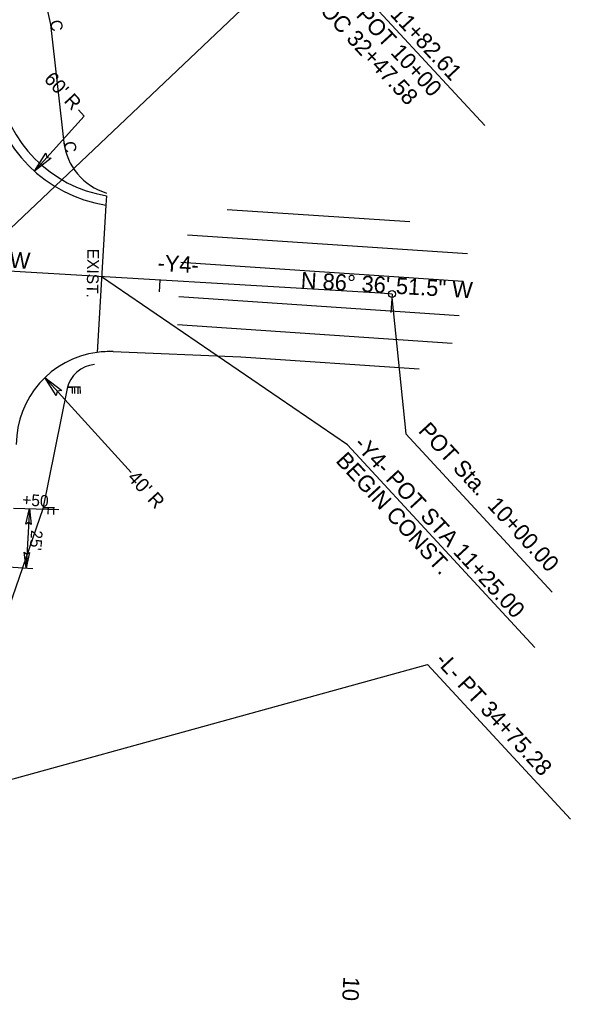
# Model space of a CAD drawing. Extents: x 1702862 to 1704514, y 793768 to 796215.
# Drawn here: x 1704008.6 to 1704245.2, y 793885.2 to 794306.9 of the extents above; entities that cross this region are included whole.
import ezdxf

# ---------------------------------------------------------------- set-up
doc = ezdxf.new("R2010")
doc.units = 0
for name, color, linetype in [('Exist Horizontal Alignment', 7, 'Continuous'), ('Prop Dimension', 7, 'Continuous'), ('Prop DSN Text', 7, 'Continuous'), ('Prop EOT', 7, 'Continuous'), ('Prop Horizontal Alignment', 7, 'Continuous'), ('Prop Horizontal Alignment Direction Label', 7, 'Continuous'), ('Prop Horizontal Alignment Station Label', 7, 'Continuous'), ('Prop Horizontal Alignment Tick Label', 7, 'Continuous'), ('Prop Horizontal Alignment Tick Large', 7, 'Continuous'), ('Prop Horizontal Alignment Tick Small', 7, 'Continuous'), ('Prop Lane Lines', 7, 'Continuous'), ('Prop Leader Line Medium', 7, 'Continuous'), ('Prop Paved Shoulder', 7, 'Continuous'), ('Prop SS Cut Line', 7, 'Continuous'), ('Prop SS Fill Line', 7, 'Continuous'), ('Prop SS Misc', 7, 'Continuous'), ('Prop SS Transition Line', 7, 'Continuous'), ('Prop Superelevation Label', 7, 'Continuous'), ('Prop Terminator CELL', 7, 'Continuous')]:
    doc.layers.add(name, color=color, linetype=linetype)

msp = doc.modelspace()

# ---------------------------------------------------------------- linework, layer by layer
at = {"layer": 'Exist Horizontal Alignment'}
msp.add_line((1704168.58, 794188.93), (1704163.59, 794189.23), dxfattribs=at)
at = {"layer": 'Prop Dimension'}
for points in [[(1704033.81, 794268.08), (1704036.35, 794265.34), (1704014.88, 794241.77)], [(1704056.52, 794112.19), (1704053.8, 794115.14), (1704019.4, 794153.02)]]:
    msp.add_lwpolyline(points, dxfattribs=at)
at = {"layer": 'Prop EOT'}
msp.add_line((1704045.63, 794227.2), (1704041.88, 794163.83), dxfattribs=at)
for centre, radius, start, end in [((1704054.89, 794286.48), 60, 188.634, 261.1171), ((1704047.11, 794124.17), 40, 97.5132, 179.9743)]:
    msp.add_arc(centre, radius, start, end, dxfattribs=at)
at = {"layer": 'Prop Horizontal Alignment'}
for p, q in [((1704163.59, 794189.23), (1703986.29, 794199.72)), ((1704168.58, 794188.93), (1704163.59, 794189.23))]:
    msp.add_line(p, q, dxfattribs=at)
at = {"layer": 'Prop Horizontal Alignment Station Label'}
for p, q in [((1703986.29, 794199.72), (1704135, 794340.88)), ((1704135, 794340.88), (1704208.42, 794261.33)), ((1704168.49, 794187.44), (1704174.54, 794128.85)), ((1704174.54, 794128.85), (1704237.37, 794060.78)), ((1703977.5, 793972.68), (1704183.79, 794029.59)), ((1704183.79, 794029.59), (1704245.2, 793963.06))]:
    msp.add_line(p, q, dxfattribs=at)
msp.add_circle((1704168.58, 794188.93), 1.5, dxfattribs=at)
at = {"layer": 'Prop Horizontal Alignment Tick Large'}
msp.add_line((1704168.58, 794188.93), (1704168.11, 794180.95), dxfattribs=at)
at = {"layer": 'Prop Horizontal Alignment Tick Small'}
msp.add_line((1704068.76, 794194.84), (1704068.46, 794189.85), dxfattribs=at)
at = {"layer": 'Prop Lane Lines'}
for p, q in [((1704097.73, 794225.32), (1704176.21, 794220.05)), ((1704080.63, 794214.44), (1704200.97, 794206.35)), ((1704077.77, 794202.61), (1704199.13, 794194.45)), ((1704076.95, 794187.8), (1704197.48, 794179.69)), ((1704076.4, 794175.81), (1704194.47, 794167.86)), ((1704048.71, 794164.14), (1704103.67, 794161.95)), ((1704103.67, 794161.95), (1704180.27, 794156.79))]:
    msp.add_line(p, q, dxfattribs=at)
msp.add_arc((1704047.11, 794124.17), 40, 87.7131, 97.5132, dxfattribs=at)
at = {"layer": 'Prop Leader Line Medium'}
for q in [(1704043.8, 794196.32), (1704229.89, 794036.99)]:
    msp.add_line((1704149.5, 794124.08), q, dxfattribs=at)
at = {"layer": 'Prop Paved Shoulder'}
msp.add_line((1704045.87, 794231.21), (1704045.63, 794227.2), dxfattribs=at)
msp.add_arc((1704054.89, 794286.48), 56, 188.634, 260.7231, dxfattribs=at)
at = {"layer": 'Prop SS Cut Line'}
for p, q in [((1704017.63, 794323.78), (1704021.82, 794304.82)), ((1704021.82, 794304.82), (1704027.73, 794252.76))]:
    msp.add_line(p, q, dxfattribs=at)
msp.add_arc((1704053.39, 794257.27), 26, 186.4769, 253.3442, dxfattribs=at)
at = {"layer": 'Prop SS Fill Line'}
msp.add_line((1704028.92, 794148.28), (1704018.54, 794096.56), dxfattribs=at)
at = {"layer": 'Prop SS Transition Line'}
msp.add_line((1704018.54, 794096.56), (1704001.25, 794046.28), dxfattribs=at)
msp.add_arc((1704041.81, 794145.42), 13.2, 94.5539, 167.5024, dxfattribs=at)
at = {"layer": 'Prop Superelevation Label'}
for p, q in [((1704005.96, 794096.86), (1704025.4, 794096.22)), ((1704012.76, 794096.63), (1704011.3, 794071.12)), ((1704003.62, 794071.57), (1704014.29, 794070.94))]:
    msp.add_line(p, q, dxfattribs=at)
for points in [[(1704011.22, 794089.96), (1704012.76, 794096.63), (1704013.57, 794089.79), (1704012.42, 794090.72)], [(1704012.85, 794077.79), (1704011.3, 794071.12), (1704010.49, 794077.96), (1704011.64, 794077.03)]]:
    msp.add_lwpolyline(points, close=True, dxfattribs=at)
at = {"layer": 'Prop Terminator CELL'}
for points in [[(1704022.09, 794247.38), (1704014.88, 794241.77), (1704019.79, 794249.54), (1704020.2, 794247.61)], [(1704024.3, 794145.32), (1704019.4, 794153.02), (1704026.67, 794147.4), (1704024.71, 794147.17)]]:
    msp.add_lwpolyline(points, close=True, dxfattribs=at)

# ---------------------------------------------------------------- texts
at = {"layer": 'Prop Dimension'}
for s, p in [("60' R", (1704018.69, 794281.06)), ("40' R", (1704054.49, 794109.65))]:
    msp.add_text(s, height=6, rotation=312.7091, dxfattribs=at).set_placement(p)
at = {"layer": 'Prop DSN Text'}
for s, height, rotation, p in [('EXIST.', 5, 268.8881, (1704037.73, 794208.46)), ('-Y4- POT STA 11+25.00', 7, 312.7091, (1704151.76, 794124.07)), ('BEGIN CONST.', 7, 312.7091, (1704144.04, 794116.95))]:
    msp.add_text(s, height=height, rotation=rotation, dxfattribs=at).set_placement(p)
at = {"layer": 'Prop Horizontal Alignment Direction Label'}
for s, p in [('N 86%%d 36\' 51.5" W', (1703939.12, 794204.07)), ('-Y4-', (1704067.67, 794198.9)), ('N 86%%d 36\' 51.5" W', (1704129.24, 794191.46))]:
    msp.add_text(s, height=7, rotation=356.6143, dxfattribs=at).set_placement(p)
at = {"layer": 'Prop Horizontal Alignment Station Label'}
for s, p in [('-Y4- POT 11+82.61', (1704138.79, 794339.98)), ('-Y4RT- POT 10+00', (1704130.56, 794332.63)), ('-L- POC 32+47.58', (1704123.51, 794325.57)), ('POT Sta.  10+00.00', (1704179.51, 794129.8)), ('-L- PT 34+75.28', (1704186.72, 794031))]:
    msp.add_text(s, height=7, rotation=312.7091, dxfattribs=at).set_placement(p)
at = {"layer": 'Prop Horizontal Alignment Tick Label'}
msp.add_text('10', height=7, rotation=266.6143, dxfattribs=at).set_placement((1704147.72, 793895.51))
at = {"layer": 'Prop SS Misc'}
for s, rotation, p in [('C', 279.8964, (1704021.56, 794306.33)), ('C', 277.0316, (1704027.54, 794254.28)), ('F', 271.3021, (1704028.88, 794149.7)), ('F', 271.3021, (1704029.8, 794149.72)), ('F', 268.4373, (1704018.57, 794097.98)), ('F', 268.4373, (1704018.57, 794097.98))]:
    msp.add_text(s, height=5, rotation=rotation, dxfattribs=at).set_placement(p)
at = {"layer": 'Prop Superelevation Label'}
for s, rotation, p in [('+50', 356.6708, (1704009.55, 794098.04)), ("25'", 266.158, (1704013.49, 794087.52))]:
    msp.add_text(s, height=5, rotation=rotation, dxfattribs=at).set_placement(p)

doc.saveas('drawing.dxf')
